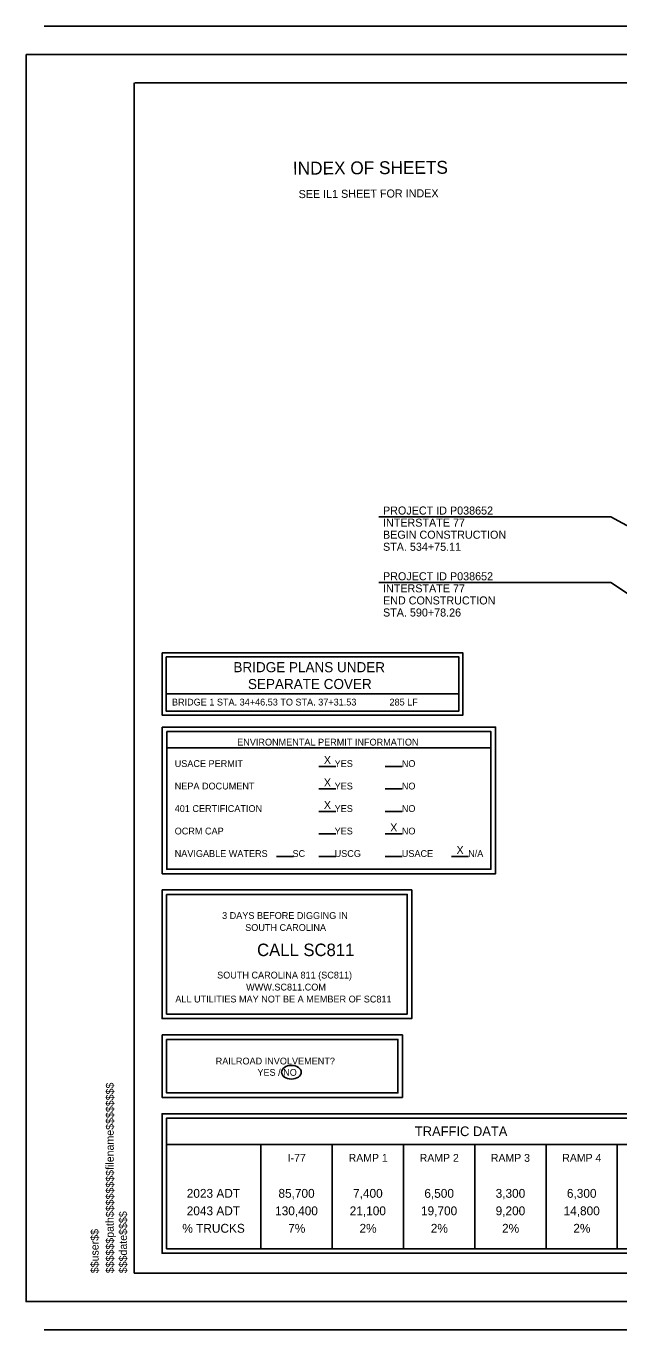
# Model space of a CAD drawing. Extents: x 1524103 to 2096450, y 1024229 to 1162569.
# Drawn here: x 2015439 to 2037540, y 1113991 to 1162569 of the extents above; entities that cross this region are included whole.
import ezdxf

# ---------------------------------------------------------------- set-up
doc = ezdxf.new("R2010")
doc.units = 0
for name, color, linetype in [('RD_SHT_Bndy', 7, 'Continuous'), ('RD_SHT_ID', 7, 'Continuous'), ('RD_SHT_IplotShp', 7, 'Continuous'), ('RD_SHT_Snap', 7, 'Continuous'), ('RD_SHT_TX', 7, 'Continuous'), ('RD_TX_TitleSht', 7, 'Continuous')]:
    doc.layers.add(name, color=color, linetype=linetype)

msp = doc.modelspace()

# ---------------------------------------------------------------- linework, layer by layer
at = {"layer": 'RD_SHT_Bndy'}
for p, q in [((2016109, 1162569), (2090454, 1162569)), ((2016109, 1161513), (2090454, 1161513)), ((2019473, 1116103), (2019473, 1160459)), ((2090245, 1160457), (2019494, 1160457)), ((2020667, 1137686), (2031569, 1137686)), ((2020675, 1120902), (2043880, 1120902)), ((2024195, 1120902), (2024195, 1117015)), ((2026852, 1120902), (2026852, 1117015)), ((2029509, 1120902), (2029509, 1117015)), ((2032166, 1120902), (2032166, 1117015)), ((2034823, 1120902), (2034823, 1117015)), ((2037480, 1120902), (2037480, 1117015)), ((2019473, 1116103), (2090264, 1116103)), ((2016109, 1115047), (2090454, 1115047)), ((2016109, 1113991), (2090454, 1113991))]:
    msp.add_line(p, q, dxfattribs=at)
for points in [[(2020517, 1139223), (2031719, 1139223), (2031719, 1136893), (2020517, 1136893)], [(2020667, 1139073), (2031569, 1139073), (2031569, 1137043), (2020667, 1137043)], [(2020510, 1130383), (2029818, 1130383), (2029818, 1125588), (2020510, 1125588)], [(2020679, 1130214), (2029649, 1130214), (2029649, 1125757), (2020679, 1125757)], [(2020509, 1124981), (2029471, 1124981), (2029471, 1122654), (2020509, 1122654)], [(2020678, 1124812), (2029302, 1124812), (2029302, 1122823), (2020678, 1122823)]]:
    msp.add_lwpolyline(points, close=True, dxfattribs=at)
at = {"layer": 'RD_SHT_IplotShp'}
msp.add_lwpolyline([(2015439, 1161513), (2091301, 1161513), (2091301, 1115047), (2015439, 1115047)], close=True, dxfattribs=at)
at = {"layer": 'RD_SHT_Snap'}
msp.add_line((2015439, 1161513), (2015439, 1115047), dxfattribs=at)
at = {"layer": 'RD_SHT_TX'}
for p, q in [((2020686, 1135680), (2032771, 1135680)), ((2026983, 1134986), (2026350, 1134986)), ((2029456, 1134985), (2028823, 1134985)), ((2026983, 1134148), (2026350, 1134148)), ((2029456, 1134147), (2028823, 1134147)), ((2026983, 1133310), (2026350, 1133310)), ((2029456, 1133309), (2028823, 1133309)), ((2026983, 1132472), (2026350, 1132472)), ((2029456, 1132471), (2028823, 1132471)), ((2025414, 1131633), (2024780, 1131633)), ((2026983, 1131633), (2026350, 1131633)), ((2029456, 1131633), (2028823, 1131633)), ((2031929, 1131633), (2031295, 1131633))]:
    msp.add_line(p, q, dxfattribs=at)
for points in [[(2020517, 1136451), (2032939, 1136451), (2032939, 1130984), (2020517, 1130984)], [(2020686, 1136282), (2032770, 1136282), (2032770, 1131153), (2020686, 1131153)], [(2044045, 1116850), (2020510, 1116850), (2020510, 1122046), (2044045, 1122046)], [(2043880, 1117015), (2020675, 1117015), (2020675, 1121881), (2043880, 1121881)]]:
    msp.add_lwpolyline(points, close=True, dxfattribs=at)
msp.add_ellipse((2025333, 1123591), major_axis=(367, 0), ratio=0.692531, dxfattribs=at)
at = {"layer": 'RD_TX_TitleSht'}
for points in [[(2028587, 1144286), (2037234, 1144286), (2046595, 1139210)], [(2028587, 1141836), (2037234, 1141836), (2048234, 1134577)]]:
    msp.add_lwpolyline(points, dxfattribs=at)

# ---------------------------------------------------------------- texts
at = {"layer": 'RD_SHT_ID'}
for s, height, p in [('$$$$$$path$$$$$$$$filename$$$$$$$$', 295.69, (2018708, 1116103)), ('$$$date$$$$', 295.69, (2019201, 1116103)), ('$$user$$', 295.7, (2018143, 1116103))]:
    msp.add_text(s, height=height, rotation=90, dxfattribs=at).set_placement(p)
at = {"layer": 'RD_SHT_TX'}
for s, height, p in [('INDEX OF SHEETS', 480, (2025388, 1157031)), ('SEE IL1 SHEET FOR INDEX', 300, (2025600, 1156159))]:
    msp.add_text(s, height=height, rotation=0.3609, dxfattribs=at).set_placement(p)
for s, height, p in [('BRIDGE PLANS UNDER', 376.36, (2023170, 1138495)), ('SEPARATE COVER', 376.36, (2023710, 1137868)), ('BRIDGE 1 STA. 34+46.53 TO STA. 37+31.53', 253.45, (2020877, 1137255)), ('285 LF', 253.5, (2028987, 1137255)), ('ENVIRONMENTAL PERMIT INFORMATION', 253.44, (2023310, 1135764)), ('USACE PERMIT', 253.44, (2020980, 1134965)), ('YES', 253.4, (2026942, 1134965)), ('NO', 253.4, (2029446, 1134965)), ('NEPA DOCUMENT', 253.44, (2020980, 1134127)), ('YES', 253.4, (2026942, 1134127)), ('NO', 253.4, (2029446, 1134127)), ('401 CERTIFICATION', 253.44, (2020980, 1133289)), ('YES', 253.4, (2026942, 1133289)), ('NO', 253.4, (2029446, 1133289)), ('OCRM CAP', 253.4, (2020980, 1132451)), ('YES', 253.4, (2026942, 1132451)), ('NO', 253.4, (2029446, 1132451)), ('NAVIGABLE WATERS', 253.44, (2020980, 1131613)), ('SC', 253.4, (2025372, 1131613)), ('USCG', 253.4, (2026942, 1131613)), ('USACE', 253.4, (2029446, 1131613)), ('N/A', 253.4, (2031919, 1131613)), ('3 DAYS BEFORE DIGGING IN', 253.45, (2022747, 1129304)), ('SOUTH CAROLINA', 253.45, (2023608, 1128857)), ('CALL SC811', 464.7, (2024050, 1127919)), ('SOUTH CAROLINA 811 (SC811)', 253.45, (2022562, 1127084)), ('WWW.SC811.COM', 253.45, (2023642, 1126637)), ('ALL UTILITIES MAY NOT BE A MEMBER OF SC811', 253.45, (2021004, 1126191)), ('RAILROAD INVOLVEMENT?', 253.45, (2022508, 1123882)), ('YES / NO', 253.5, (2024063, 1123459)), ('TRAFFIC DATA', 360, (2029932, 1121212)), ('I-77', 292.7, (2025192, 1120255)), ('RAMP 1', 292.7, (2027465, 1120255)), ('RAMP 2', 292.7, (2030114, 1120255)), ('RAMP 3', 292.7, (2032766, 1120255)), ('RAMP 4', 292.7, (2035428, 1120255)), ('2023 ADT', 330, (2021429, 1118914)), ('2043 ADT', 330, (2021429, 1118263)), ('% TRUCKS', 330, (2021264, 1117612))]:
    msp.add_text(s, height=height, dxfattribs=at).set_placement(p)
at = {"layer": 'RD_TX_TitleSht'}
for s, height, p in [('PROJECT ID P038652', 300, (2028745, 1144369)), ('INTERSTATE 77', 300, (2028745, 1143919)), ('BEGIN CONSTRUCTION', 300, (2028745, 1143469)), ('STA. 534+75.11', 300, (2028745, 1143019)), ('PROJECT ID P038652', 300, (2028745, 1141920)), ('INTERSTATE 77', 300, (2028745, 1141470)), ('END CONSTRUCTION', 300, (2028745, 1141020)), ('STA. 590+78.26', 300, (2028745, 1140570)), ('X', 300, (2026539, 1135076)), ('X', 300, (2026539, 1134238)), ('X', 300, (2026539, 1133400)), ('X', 300, (2029012, 1132561)), ('X', 300, (2031485, 1131723)), ('85,700', 330, (2024847, 1118914)), ('7,400', 330, (2027629, 1118914)), ('6,500', 330, (2030286, 1118914)), ('3,300', 330, (2032943, 1118914)), ('6,300', 330, (2035600, 1118914)), ('130,400', 330, (2024723, 1118263)), ('21,100', 330, (2027504, 1118263)), ('19,700', 330, (2030161, 1118263)), ('9,200', 330, (2032943, 1118263)), ('14,800', 330, (2035476, 1118263)), ('7%', 330, (2025212, 1117612)), ('2%', 330, (2027869, 1117612)), ('2%', 330, (2030526, 1117612)), ('2%', 330, (2033183, 1117612)), ('2%', 330, (2035840, 1117612))]:
    msp.add_text(s, height=height, dxfattribs=at).set_placement(p)

doc.saveas('drawing.dxf')
